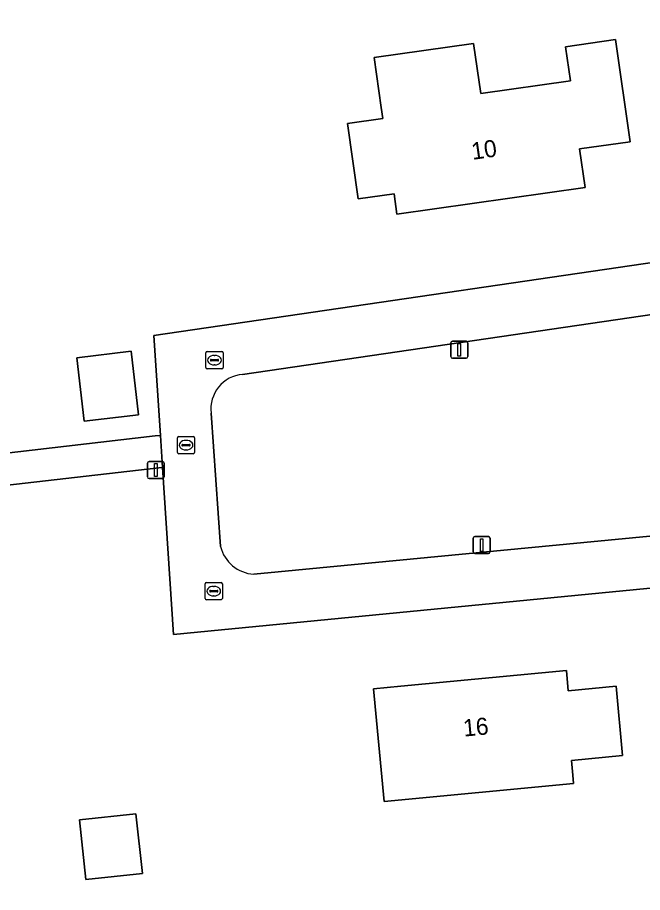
# Model space of a CAD drawing. Extents: x 162661 to 163484, y 380247 to 381230.
# Drawn here: x 163055.7 to 163092.2, y 380630.3 to 380681.5 of the extents above; entities that cross this region are included whole.
import ezdxf

# ---------------------------------------------------------------- set-up
doc = ezdxf.new("R2010")
doc.units = 0
for name, color, linetype in [('IMGEO_Brandkraan', 7, 'Continuous'), ('IMGEO_Erf', 7, 'Continuous'), ('IMGEO_Groenvoorziening', 7, 'Continuous'), ('IMGEO_Lichtmast', 7, 'Continuous'), ('IMGEO_Pand', 7, 'Continuous'), ('IMGEO_Pand_nummerreeks', 7, 'Continuous'), ('IMGEO_Rijbaan_lokaal_open', 7, 'Continuous'), ('IMGEO_Rioolput', 7, 'Continuous'), ('IMGEO_Voetpad_open', 7, 'Continuous')]:
    doc.layers.add(name, color=color, linetype=linetype)

msp = doc.modelspace()

# ---------------------------------------------------------------- linework, layer by layer
at = {"layer": 'IMGEO_Brandkraan'}
for p, q in [((163065.053, 380656.043), (163065.053, 380656.895)), ((163065.128, 380656.969), (163065.98, 380656.969)), ((163065.541, 380656.749), (163065.566, 380656.749)), ((163066.054, 380656.895), (163066.054, 380656.043)), ((163065.312, 380656.463), (163065.312, 380656.475)), ((163065.75, 380656.426), (163065.352, 380656.426)), ((163065.355, 380656.512), (163065.753, 380656.512)), ((163065.564, 380656.189), (163065.539, 380656.189)), ((163065.796, 380656.475), (163065.796, 380656.463)), ((163065.98, 380655.969), (163065.128, 380655.969))]:
    msp.add_line(p, q, dxfattribs=at)
for points in [[(163065.053, 380656.043), (163065.053, 380656.895)], [(163065.128, 380656.969), (163065.98, 380656.969)], [(163066.054, 380656.895), (163066.054, 380656.043)], [(163065.98, 380655.969), (163065.128, 380655.969)]]:
    msp.add_lwpolyline(points, dxfattribs=at)
for centre, radius, start, end in [((163065.13, 380656.893), 0.0765, 91.552, 178.448), ((163065.13, 380656.893), 0.0765, 91.552, 178.448), ((163065.978, 380656.893), 0.0765, 1.552, 88.448), ((163065.978, 380656.893), 0.0765, 1.552, 88.448), ((163065.13, 380656.045), 0.0765, 181.552, 268.448), ((163065.13, 380656.045), 0.0765, 181.552, 268.448), ((163065.352, 380656.472), 0.0403, 85.8775, 175.7526), ((163065.349, 380656.462), 0.0366, 178.938, 274.7102), ((163065.753, 380656.469), 0.043, 264.8664, 352.4533), ((163065.757, 380656.474), 0.0386, 1.7309, 96.639), ((163065.978, 380656.045), 0.0765, 271.552, 358.448), ((163065.978, 380656.045), 0.0765, 271.552, 358.448)]:
    msp.add_arc(centre, radius, start, end, dxfattribs=at)
for centre, major_axis, ratio, start_param, end_param in [((163065.54, 380656.469), (-0.387, 0.002), 0.722429, 4.712389, 7.853982), ((163065.565, 380656.469), (-0.39, 0.002), 0.717154, 1.570796, 4.712389)]:
    msp.add_ellipse(centre, major_axis=major_axis, ratio=ratio, start_param=start_param, end_param=end_param, dxfattribs=at)
at = {"layer": 'IMGEO_Erf'}
for points in [[(163099.255, 380695.881), (163097.801, 380713.922), (163097.793, 380714.023), (163096.429, 380713.908), (163093.637, 380713.673), (163059.39, 380710.863), (163058.898, 380719.038), (163058.632, 380719.002), (163032.944, 380715.524), (163037.315, 380653.943), (163063.757, 380657.004), (163064.055, 380657.039), (163063.669, 380662.881), (163100.129, 380668.22), (163101.186, 380668.378), (163101.16, 380668.743)], [(163076.967, 380676.192), (163076.556, 380679.109), (163082.364, 380679.928), (163082.776, 380677.011), (163088.02, 380677.751), (163087.739, 380679.747), (163090.667, 380680.16), (163091.508, 380674.192), (163088.561, 380673.776), (163088.88, 380671.518), (163077.877, 380669.967), (163077.711, 380671.146), (163075.622, 380670.852), (163075.001, 380675.266), (163077.057, 380675.555)], [(163059.168, 380661.576), (163062.343, 380661.949), (163062.778, 380658.24), (163059.604, 380657.867)], [(163104.464, 380649.238), (163101.514, 380648.96), (163064.825, 380645.41), (163064.179, 380655.165), (163063.957, 380655.14), (163037.446, 380652.111), (163041.973, 380588.769), (163067.753, 380591.633), (163067.425, 380594.839), (163070.153, 380595.118), (163070.481, 380591.912), (163070.696, 380591.934), (163070.695, 380591.946), (163070.09, 380598.191), (163102.911, 380602.998), (163106.144, 380603.482), (163108.863, 380603.734), (163108.827, 380604.097)], [(163077.138, 380635.654), (163076.519, 380642.231), (163078.108, 380642.381), (163087.787, 380643.295), (163087.898, 380642.117), (163090.688, 380642.381), (163091.07, 380638.329), (163088.076, 380638.046), (163088.157, 380637.192), (163088.204, 380636.699)], [(163059.329, 380634.572), (163062.628, 380634.927), (163063.004, 380631.437), (163059.704, 380631.082)]]:
    msp.add_lwpolyline(points, close=True, dxfattribs=at)
at = {"layer": 'IMGEO_Groenvoorziening'}
for points in [[(163069.509, 380648.927), (163101.8, 380652.027), (163101.745, 380652.433), (163100.558, 380664.802), (163100.497, 380665.225), (163068.853, 380660.603)], [(163067.016, 380658.343), (163067.57, 380650.541)]]:
    msp.add_lwpolyline(points, dxfattribs=at)
for centre, radius, start, end in [((163069.042, 380658.573), 2.039, 95.3254, 186.464), ((163069.638, 380651.053), 2.13, 193.9175, 266.5354)]:
    msp.add_arc(centre, radius, start, end, dxfattribs=at)
at = {"layer": 'IMGEO_Lichtmast'}
for p, q in [((163081.03, 380661.641), (163081.03, 380662.441)), ((163081.03, 380662.441), (163081.03, 380661.641)), ((163081.13, 380662.541), (163081.92, 380662.541)), ((163081.92, 380662.541), (163081.13, 380662.541)), ((163082.02, 380662.441), (163082.02, 380661.641)), ((163082.02, 380661.641), (163082.02, 380662.441)), ((163081.92, 380661.541), (163081.13, 380661.541)), ((163081.13, 380661.541), (163081.92, 380661.541)), ((163063.393, 380655.511), (163064.183, 380655.511)), ((163064.183, 380655.511), (163063.393, 380655.511)), ((163063.293, 380654.611), (163063.293, 380655.411)), ((163063.293, 380655.411), (163063.293, 380654.611)), ((163064.283, 380655.411), (163064.283, 380654.611)), ((163064.283, 380654.611), (163064.283, 380655.411)), ((163064.183, 380654.511), (163063.393, 380654.511)), ((163063.393, 380654.511), (163064.183, 380654.511)), ((163082.337, 380650.228), (163082.337, 380651.028)), ((163082.337, 380651.028), (163082.337, 380650.228)), ((163082.437, 380651.128), (163083.227, 380651.128)), ((163083.227, 380651.128), (163082.437, 380651.128)), ((163083.327, 380651.028), (163083.327, 380650.228)), ((163083.327, 380650.228), (163083.327, 380651.028)), ((163083.227, 380650.128), (163082.437, 380650.128)), ((163082.437, 380650.128), (163083.227, 380650.128))]:
    msp.add_line(p, q, dxfattribs=at)
for points in [[(163081.45, 380662.416), (163081.6, 380662.416), (163081.6, 380661.666), (163081.45, 380661.666), (163081.45, 380662.416)], [(163063.713, 380655.386), (163063.863, 380655.386), (163063.863, 380654.636), (163063.713, 380654.636), (163063.713, 380655.386)], [(163082.757, 380651.003), (163082.907, 380651.003), (163082.907, 380650.253), (163082.757, 380650.253), (163082.757, 380651.003)]]:
    msp.add_lwpolyline(points, dxfattribs=at)
for centre, start, end in [((163081.13, 380662.441), 90, 180), ((163081.13, 380662.441), 90, 180), ((163081.92, 380662.441), 0, 90), ((163081.92, 380662.441), 360, 90), ((163081.13, 380661.641), 180, 270), ((163081.13, 380661.641), 180, 270), ((163081.92, 380661.641), 270, 0), ((163081.92, 380661.641), 270, 0), ((163063.393, 380655.411), 90, 180), ((163063.393, 380655.411), 90, 180), ((163064.183, 380655.411), 0, 90), ((163064.183, 380655.411), 360, 90), ((163063.393, 380654.611), 180, 270), ((163063.393, 380654.611), 180, 270), ((163064.183, 380654.611), 270, 0), ((163064.183, 380654.611), 270, 0), ((163082.437, 380651.028), 90, 180), ((163082.437, 380651.028), 90, 180), ((163083.227, 380651.028), 0, 90), ((163083.227, 380651.028), 360, 90), ((163082.437, 380650.228), 180, 270), ((163082.437, 380650.228), 180, 270), ((163083.227, 380650.228), 270, 0), ((163083.227, 380650.228), 270, 0)]:
    msp.add_arc(centre, 0.1, start, end, dxfattribs=at)
at = {"layer": 'IMGEO_Pand'}
for points in [[(163076.967, 380676.192), (163077.057, 380675.555), (163075.001, 380675.266), (163075.622, 380670.852), (163077.711, 380671.146), (163077.877, 380669.967), (163088.88, 380671.518), (163088.561, 380673.776), (163091.508, 380674.192), (163090.667, 380680.16), (163087.739, 380679.747), (163088.02, 380677.751), (163082.776, 380677.011), (163082.364, 380679.928), (163076.556, 380679.109)], [(163059.168, 380661.576), (163059.604, 380657.867), (163062.778, 380658.24), (163062.343, 380661.949)], [(163090.688, 380642.381), (163087.898, 380642.117), (163087.787, 380643.295), (163078.108, 380642.381), (163076.519, 380642.231), (163077.138, 380635.654), (163088.204, 380636.699), (163088.157, 380637.192), (163088.076, 380638.046), (163091.07, 380638.329)], [(163059.329, 380634.572), (163059.704, 380631.082), (163063.004, 380631.437), (163062.628, 380634.927)]]:
    msp.add_lwpolyline(points, close=True, dxfattribs=at)
at = {"layer": 'IMGEO_Rijbaan_lokaal_open'}
for points in [[(163068.853, 380660.603), (163100.497, 380665.225), (163100.129, 380668.22), (163063.669, 380662.881), (163064.055, 380657.039), (163064.179, 380655.165), (163064.825, 380645.41), (163101.514, 380648.96), (163101.8, 380652.027), (163069.509, 380648.927)], [(163067.57, 380650.541), (163067.016, 380658.343)]]:
    msp.add_lwpolyline(points, dxfattribs=at)
for centre, radius, start, end in [((163069.042, 380658.573), 2.039, 95.3254, 186.464), ((163069.638, 380651.053), 2.13, 193.9175, 266.5354)]:
    msp.add_arc(centre, radius, start, end, dxfattribs=at)
at = {"layer": 'IMGEO_Rioolput'}
for p, q in [((163066.717, 380661.007), (163066.717, 380661.859)), ((163066.792, 380661.933), (163067.644, 380661.933)), ((163067.205, 380661.713), (163067.23, 380661.713)), ((163067.718, 380661.859), (163067.718, 380661.007)), ((163066.976, 380661.427), (163066.976, 380661.439)), ((163067.414, 380661.39), (163067.016, 380661.39)), ((163067.019, 380661.476), (163067.417, 380661.476)), ((163067.228, 380661.153), (163067.203, 380661.153)), ((163067.46, 380661.439), (163067.46, 380661.427)), ((163067.644, 380660.933), (163066.792, 380660.933)), ((163066.676, 380647.512), (163066.676, 380648.364)), ((163066.751, 380648.438), (163067.603, 380648.438)), ((163067.677, 380648.364), (163067.677, 380647.512)), ((163066.935, 380647.932), (163066.935, 380647.944)), ((163067.373, 380647.895), (163066.975, 380647.895)), ((163066.978, 380647.981), (163067.376, 380647.981)), ((163067.164, 380648.218), (163067.189, 380648.218)), ((163067.419, 380647.944), (163067.419, 380647.932)), ((163067.603, 380647.438), (163066.751, 380647.438)), ((163067.187, 380647.658), (163067.162, 380647.658))]:
    msp.add_line(p, q, dxfattribs=at)
for points in [[(163066.717, 380661.007), (163066.717, 380661.859)], [(163066.792, 380661.933), (163067.644, 380661.933)], [(163067.718, 380661.859), (163067.718, 380661.007)], [(163067.644, 380660.933), (163066.792, 380660.933)], [(163066.676, 380647.512), (163066.676, 380648.364)], [(163066.751, 380648.438), (163067.603, 380648.438)], [(163067.677, 380648.364), (163067.677, 380647.512)], [(163067.603, 380647.438), (163066.751, 380647.438)]]:
    msp.add_lwpolyline(points, dxfattribs=at)
for centre, radius, start, end in [((163066.794, 380661.857), 0.0765, 91.552, 178.448), ((163066.794, 380661.857), 0.0765, 91.552, 178.448), ((163067.642, 380661.857), 0.0765, 1.552, 88.448), ((163067.642, 380661.857), 0.0765, 1.552, 88.448), ((163067.016, 380661.436), 0.0403, 85.8775, 175.7526), ((163067.013, 380661.426), 0.0366, 178.938, 274.7102), ((163067.417, 380661.433), 0.043, 264.8664, 352.4533), ((163067.421, 380661.438), 0.0386, 1.7309, 96.639), ((163066.794, 380661.009), 0.0765, 181.552, 268.448), ((163066.794, 380661.009), 0.0765, 181.552, 268.448), ((163067.642, 380661.009), 0.0765, 271.552, 358.448), ((163067.642, 380661.009), 0.0765, 271.552, 358.448), ((163066.753, 380648.362), 0.0765, 91.552, 178.448), ((163066.753, 380648.362), 0.0765, 91.552, 178.448), ((163067.601, 380648.362), 0.0765, 1.552, 88.448), ((163067.601, 380648.362), 0.0765, 1.552, 88.448), ((163066.975, 380647.941), 0.0403, 85.8775, 175.7526), ((163066.972, 380647.931), 0.0366, 178.938, 274.7102), ((163067.376, 380647.938), 0.043, 264.8664, 352.4533), ((163067.38, 380647.943), 0.0386, 1.7309, 96.639), ((163066.753, 380647.514), 0.0765, 181.552, 268.448), ((163066.753, 380647.514), 0.0765, 181.552, 268.448), ((163067.601, 380647.514), 0.0765, 271.552, 358.448), ((163067.601, 380647.514), 0.0765, 271.552, 358.448)]:
    msp.add_arc(centre, radius, start, end, dxfattribs=at)
for centre, major_axis, ratio, start_param, end_param in [((163067.204, 380661.433), (-0.387, 0.002), 0.722429, 4.712389, 7.853982), ((163067.229, 380661.433), (-0.39, 0.002), 0.717154, 1.570796, 4.712389), ((163067.163, 380647.938), (-0.387, 0.002), 0.722429, 4.712389, 7.853982), ((163067.188, 380647.938), (-0.39, 0.002), 0.717154, 1.570796, 4.712389)]:
    msp.add_ellipse(centre, major_axis=major_axis, ratio=ratio, start_param=start_param, end_param=end_param, dxfattribs=at)
at = {"layer": 'IMGEO_Voetpad_open'}
msp.add_lwpolyline([(163070.497, 380590.125), (163070.867, 380590.166), (163070.696, 380591.934), (163070.481, 380591.912), (163067.753, 380591.633), (163041.973, 380588.769), (163037.446, 380652.111), (163063.957, 380655.14), (163064.179, 380655.165), (163064.055, 380657.039), (163063.757, 380657.004), (163037.315, 380653.943), (163032.944, 380715.524), (163058.632, 380719.002), (163058.898, 380719.038), (163058.785, 380720.911), (163058.503, 380720.872), (163032.814, 380717.345), (163030.493, 380750), (163029.443, 380764.786), (163028.665, 380775.858), (163028.488, 380778.563), (163028.12, 380778.882)], dxfattribs=at)

# ---------------------------------------------------------------- texts
at = {"layer": 'IMGEO_Pand_nummerreeks'}
for s, rotation, p in [('10', 8.0236, (163082.302, 380673.135)), ('16', 5.3915, (163081.796, 380639.435))]:
    msp.add_text(s, height=1, rotation=rotation, dxfattribs=at).set_placement(p)

doc.saveas('drawing.dxf')
